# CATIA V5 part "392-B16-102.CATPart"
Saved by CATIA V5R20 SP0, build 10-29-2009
Part number: 392-B16-102
Definition: NONE
Nomenclature: 392-B16-102
Source: Unknown
Description: 392-B16-102
Bounding box of the stored display mesh (mm): x 0 to 102, y -7.677 to 7.677, z -7.6 to 7.409
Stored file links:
  C:\Users\Utente\Desktop\IO LAVORO\3D X SITO CF\X SITO\3D files 392B\392-B16-102.CATPart
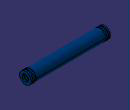
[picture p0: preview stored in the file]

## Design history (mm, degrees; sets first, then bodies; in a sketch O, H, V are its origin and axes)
Body1 "392-B16-102" (main body)
  Solid1: solid without history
